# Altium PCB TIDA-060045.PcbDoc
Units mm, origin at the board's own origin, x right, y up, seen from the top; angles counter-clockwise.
Board outline 105 x 122.75 mm, 4 copper layers (Top Layer, Int1 (GND), Int2 (PWR), Bottom Layer), stack 1.547 mm thick; 49 components, 26 nets, 141 pads, 38 vias.
Unrouted connection lines stored in the file: 12.
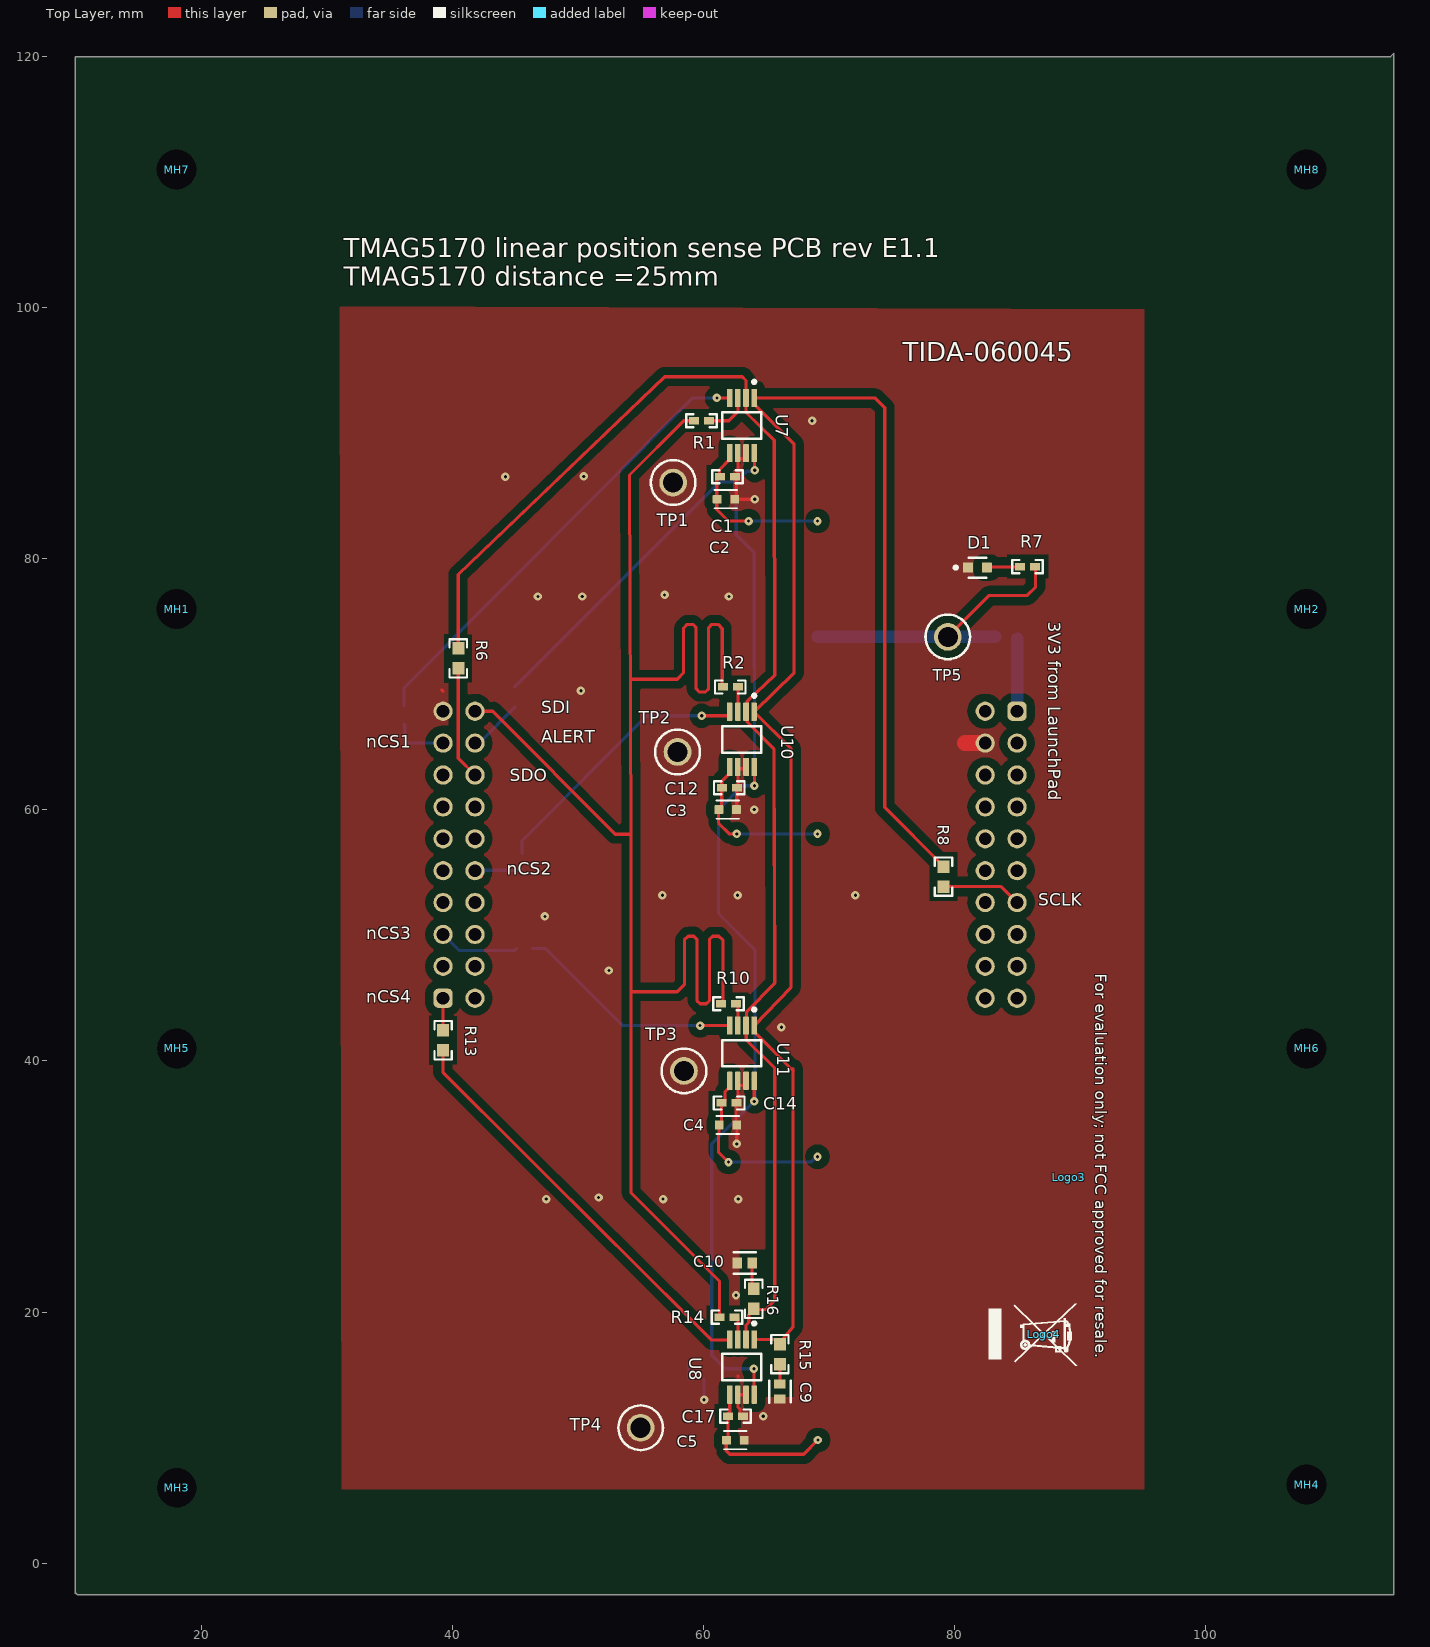
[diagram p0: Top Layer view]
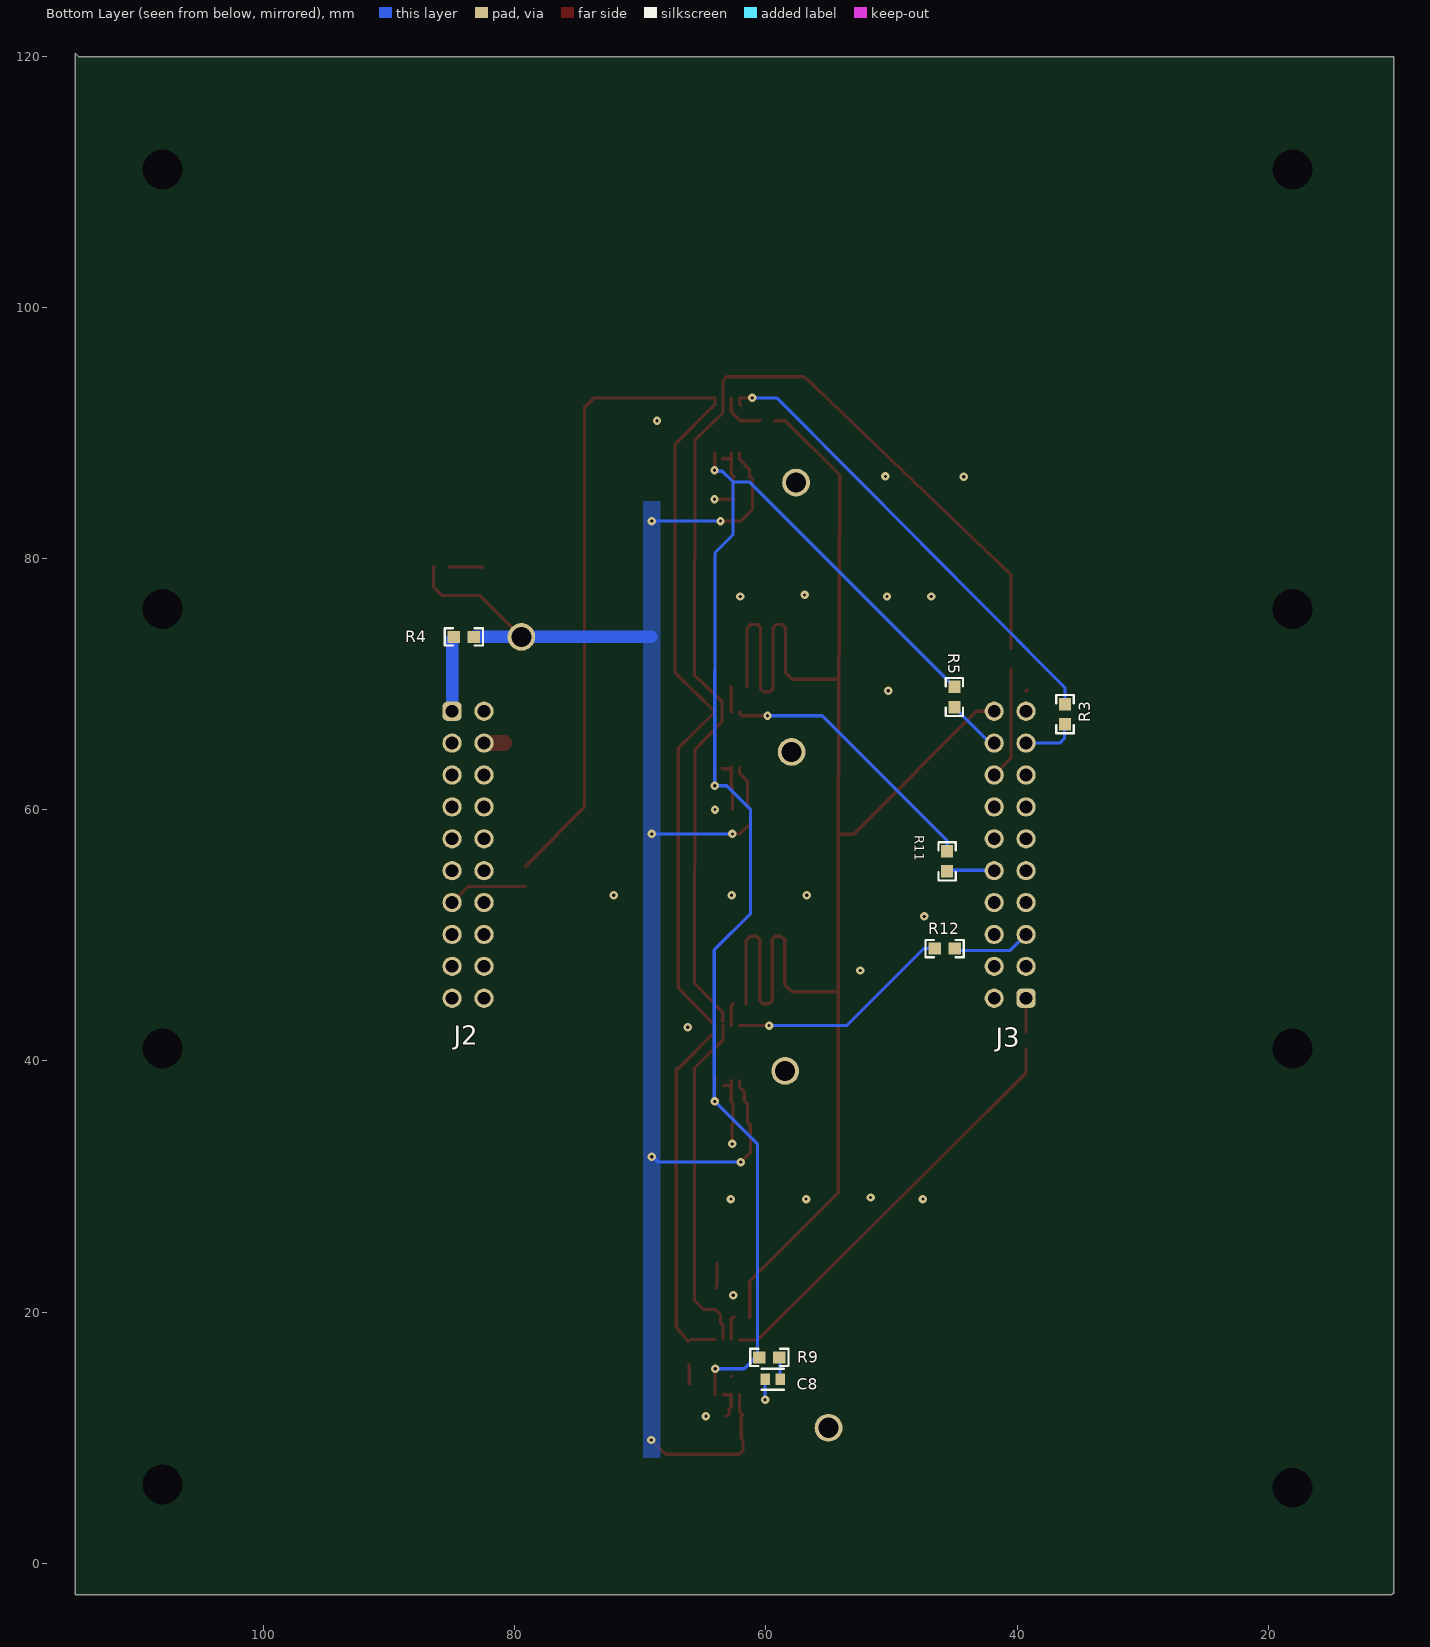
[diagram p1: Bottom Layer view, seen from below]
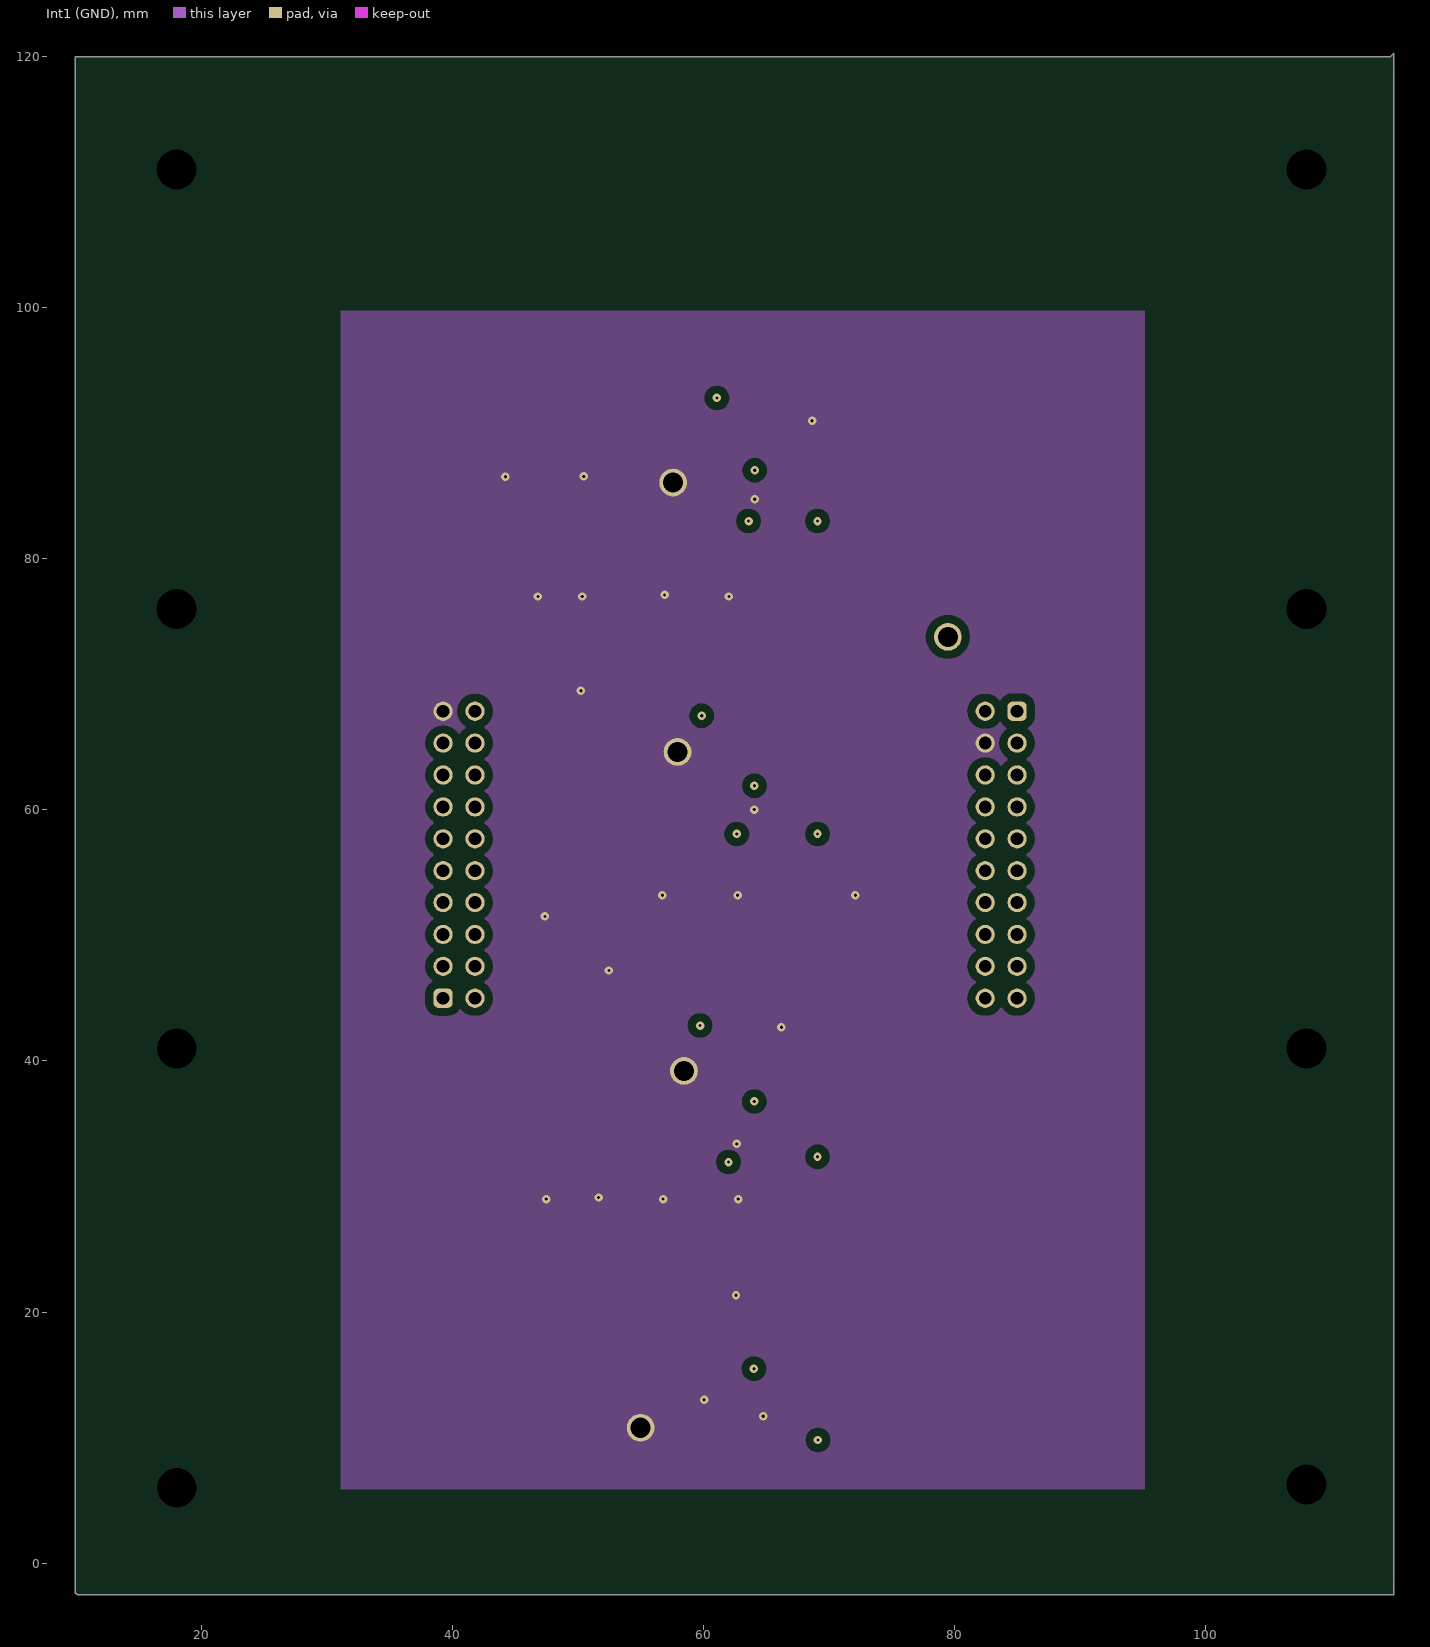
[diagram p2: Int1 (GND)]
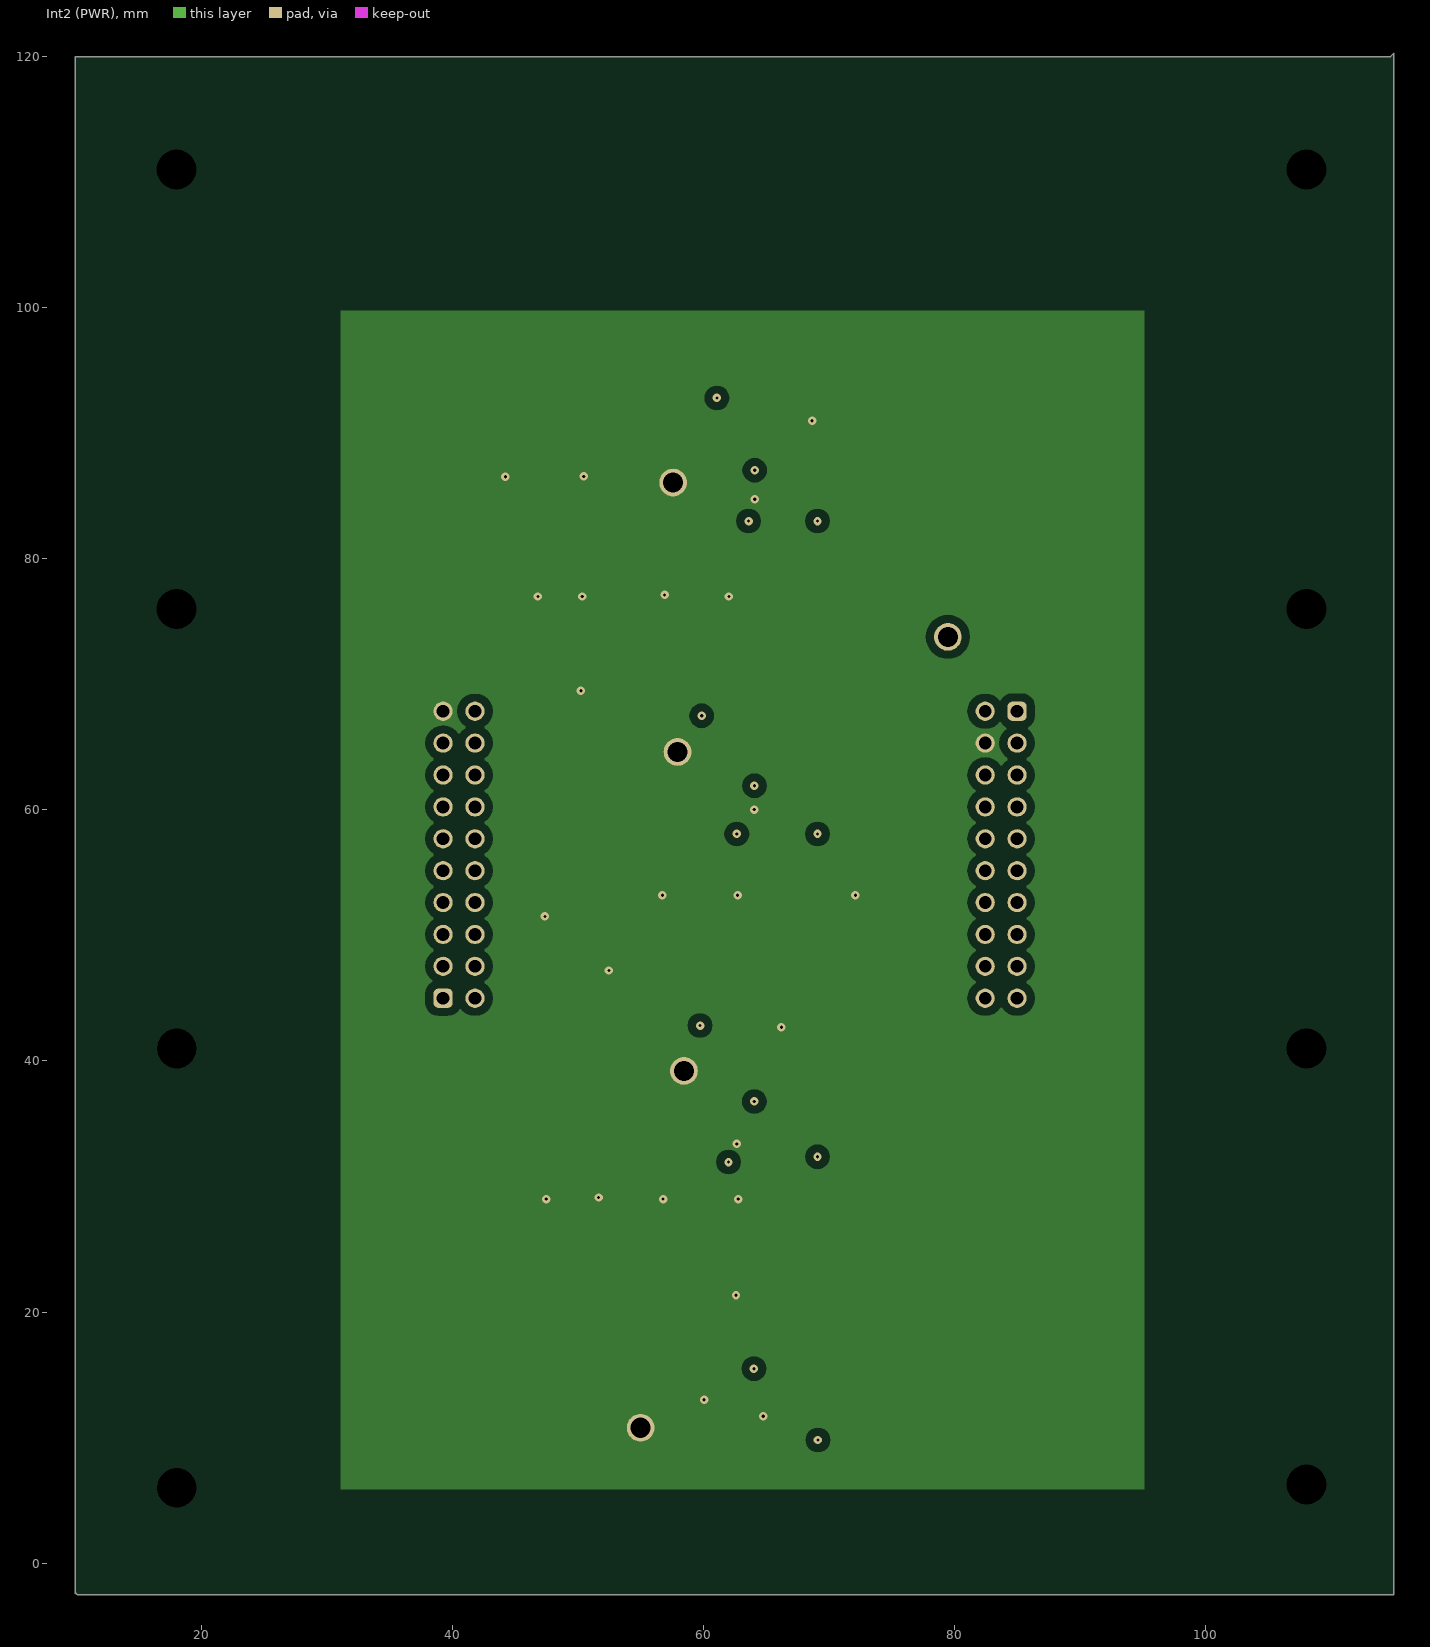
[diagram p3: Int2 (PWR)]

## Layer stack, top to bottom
Top Solder: solder mask 0.0254, SM-001, Dk 4
Top Layer: signal copper 0.035
Dielectric 1: prepreg 0.2083, PP-022, Dk 4.5
Int1 (GND): signal copper 0.035
Dielectric 3: core 0.9906, Core-042, Dk 4.6
Int2 (PWR): signal copper 0.035
Dielectric 5: prepreg 0.2083, PP-022, Dk 4.5
Bottom Layer: signal copper 0.035
Bottom Solder: solder mask 0.0254, SM-001, Dk 4

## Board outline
10,-2.353 10.147,-2.5 115,-2.5 115,120.25 114.75,120 10,120 10,-2.451

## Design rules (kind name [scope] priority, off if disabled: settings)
AcuteAngle [All] p1: minimum=4.50000000000000E+0001 checktracksonly=FALSE
AssemblyTestPointUsage [All] p1: valid=2
BoardOutlineClearance BoardOutlineClearance_MountingHoles [OnCopper and InComponentClass('Mounting Holes')] p1: gap=1 ignorepadtopadclearanceinfootprint=FALSE
BoardOutlineClearance BoardOutlineClearance_Poly [OnCopper and IsPoly] p2: gap=0.635 ignorepadtopadclearanceinfootprint=FALSE
BoardOutlineClearance [OnCopper and Not InComponentClass('Logo') and not InComponentClass('FiducialMark') and not InRegion(1000,500,4000,800) and not InPoly] p3: gap=1.905 ignorepadtopadclearanceinfootprint=FALSE
Clearance Clearance_Keepouts [((IsTrack Or IsArc) And Not InPoly) And IsFree and IsKeepOut vs ((IsTrack Or IsArc) And Not InPoly) And IsFree and IsKeepOut] p1: gap=0 ignorepadtopadclearanceinfootprint=FALSE
Clearance Clearance_Poly [InPolygon] p2: gap=0.635 ignorepadtopadclearanceinfootprint=TRUE
Clearance Clearance_FiducialMark [IsKeepOut and InComponentClass('FiducialMark') vs IsPad and InComponentClass('FiducialMark')] p3: gap=0 ignorepadtopadclearanceinfootprint=FALSE
Clearance [All] p4: gap=0.1 ignorepadtopadclearanceinfootprint=TRUE
ComponentClearance ComponentClearance_MountingHoles_FiducialMarks [InComponentClass('Mounting Holes') vs InComponentClass('FiducialMark')] p1: gap=1.27 collisioncheckmode=3 verticalgap=0.254 showdistances=FALSE
ComponentClearance ComponentClearance_Shunt [InComponentClass('Header') vs InComponentClass('Shunt')] p2: gap=0 collisioncheckmode=3 verticalgap=0 showdistances=FALSE
ComponentClearance ComponentClearance_Logo [InComponentClass('Logo')] p3: gap=1.27 collisioncheckmode=3 verticalgap=0.254 showdistances=FALSE
ComponentClearance ComponentClearance_ScrewToNut [(HasFootprint('NY PMS 440 0025 PH')) vs (HasFootprint('Keystone_1902C'))] p4: gap=0.127 collisioncheckmode=3 verticalgap=0.254 showdistances=FALSE
ComponentClearance ComponentClearance_MountingHoles [InComponentClass('Mounting Holes')] p5: gap=6.35 collisioncheckmode=3 verticalgap=2540 showdistances=FALSE
ComponentClearance ComponentClearance_SmallPassives [HasFootprint('0201*') or HasFootprint('0402*') or HasFootprint('0508') or HasFootprint('0603*') or HasFootprint('0612') or HasFootprint('0805*') or HasFootprint('0815*') or HasFootprint('0830*') or HasFootprint('1206*') or HasFootprint('1210*') or HasFootprint('1808*') or HasFootprint('1812*') or HasFootprint('1825*') or HasFootprint('2010*') or HasFootprint('2220*') or HasFootprint('2225*') or HasFootprint('2512*') or HasFootprint('2728*') or HasFootprint('3518*') vs HasFootprint('0201*') or HasFootprint('0402*') or HasFootprint('0508') or HasFootprint('0603*') or HasFootprint('0612') or HasFootprint('0805*') or HasFootprint('0815*') or HasFootprint('0830*') or HasFootprint('1206*') or HasFootprint('1210*') or HasFootprint('1808*') or HasFootprint('1812*') or HasFootprint('1825*') or HasFootprint('2010*') or HasFootprint('2220*') or HasFootprint('2225*') or HasFootprint('2512*') or HasFootprint('2728*') or HasFootprint('3518*')] p6: gap=0.38 collisioncheckmode=3 verticalgap=0.254 showdistances=FALSE
ComponentClearance ComponentClearance_THtoSMT [IsThruComponent vs IsSMTComponent] p7: gap=1.016 collisioncheckmode=3 verticalgap=0.762 showdistances=FALSE
ComponentClearance ComponentClearance_THtoTH [IsThruComponent vs IsThruComponent] p8: gap=0.762 collisioncheckmode=3 verticalgap=0.762 showdistances=FALSE
ComponentClearance [All] p9: gap=0.762 collisioncheckmode=3 verticalgap=0.254 showdistances=FALSE
DiffPairsRouting [All] p1: maxlimit=2.54 minlimit=0.254 mostfreqgap=0.254 toplayer_minwidth=0.381 toplayer_maxwidth=0.381 toplayer_prefwidth=0.381 midlayer1_minwidth=0.381 midlayer1_maxwidth=0.381 midlayer1_prefwidth=0.381 midlayer2_minwidth=0.381 midlayer2_maxwidth=0.381 midlayer2_prefwidth=0.381 bottomlayer_minwidth=0.381 bottomlayer_maxwidth=0.381 bottomlayer_prefwidth=0.381 maxuncoupledlength=25.4
FabricationTestPointUsage TestPointUsage [All] p1: valid=2 allowmultiple=FALSE
FabricationTestpoint Testpoint [All] p1: side=3 testpointundercomponent=TRUE minsize=1.016 maxsize=2.54 preferedsize=1.524 minholesize=0 maxholesize=1.016 preferedholesize=0.813 testpointgrid=0.025 allowsidetop=TRUE allowsidebottom=TRUE usegrid=TRUE gridtolerance=0
FanoutControl Fanout_LCC [IsLCC] p1: bgadir=Out bgaviamode=Centered fanoutstyle=Auto fanoutdirection=Alternating viagrid=0.025 // Fanout_LCC (Default Rule)
FanoutControl Fanout_BGA [IsBGA] p2: bgadir=Out bgaviamode=Centered fanoutstyle=Auto fanoutdirection=Alternating viagrid=0.025 // Fanout_BGA (Default Rule)
FanoutControl Fanout_Default [All] p4: bgadir=Out bgaviamode=Centered fanoutstyle=Auto fanoutdirection=Alternating viagrid=0.025 // Fanout_Default (Default Rule)
FanoutControl Fanout_Small [(CompPinCount < 5)] p5: bgadir=Out bgaviamode=Centered fanoutstyle=Auto fanoutdirection=OutThenIn viagrid=0.025 // Fanout_Small (Default Rule)
HoleSize [All] p1: absolutevalues=TRUE maxlimit=6.375 minlimit=0.2 maxpercent=80.000 minpercent=20.000
MinimumAnnularRing MinimumAnnularRing_ThermalPadVias [IsVia and InAnyComponent] p1: minimumring=0.15
MinimumAnnularRing [All] p2: minimumring=0.2
MinimumSolderMaskSliver MinimumSolderMaskSliver_Logo [InComponentClass('Logo') vs InComponentClass('Logo')] p1: minsoldermaskwidth=0.018
MinimumSolderMaskSliver [All] p2: minsoldermaskwidth=0.1
PlaneConnect [All] p1: planeconnectstyle=Direct reliefexpansion=0.254 reliefentries=4 reliefconductorwidth=0.254 reliefairgap=0.254
PolygonConnect [All] p1: connectstyle=Direct reliefconductorwidth=0.254 reliefentries=4 polygonreliefangle="90 Angle" airgapwidth=0.254
RoutingLayers [All] p1: top layer_v5=TRUE mid layer 1_v5=FALSE mid layer 2_v5=FALSE bottom layer_v5=TRUE
RoutingVias ThermalPadVias [IsVia and InAnyComponent] p1: holewidth=0.2 width=0.5 viastyle="Through Hole" minholewidth=0.2 minwidth=0.5 maxholewidth=0.33 maxwidth=0.6
RoutingVias [All] p2: holewidth=0.406 width=0.864 viastyle="Through Hole" minholewidth=0.2 minwidth=0.66 maxholewidth=1.016 maxwidth=1.651
SilkToBoardRegionClearance [Not ((IsComment or IsDesignator) And (Hide <> 'False')) and not InRegion(1000,500,4000,800)] p1:
SilkToSilkClearance SilkToSilkClearance_Pb-FreeLogo [(HasFootprint('Pb-Free_Overlay_Medium') OR HasFootprint('Pb-Free_Overlay_Small')) vs (HasFootprint('Pb-Free_Overlay_Medium') OR HasFootprint('Pb-Free_Overlay_Small'))] p1: silktosilkclearance=0
SilkToSilkClearance [All] p2: silktosilkclearance=0.1
SilkToSolderMaskClearance SilkToComponentPadClearance [(IsPad or IsFill or IsRegion) and InAnycomponent] p1: minsilkscreentomaskgap=0.127 clearancetoexposedcopper=TRUE
SilkToSolderMaskClearance "Silk to Solder Mask Opening" [All] p2: minsilkscreentomaskgap=0.1 clearancetoexposedcopper=FALSE
SolderMaskExpansion [All] p1: expansion=0.05 istentingtop=FALSE
UnRoutedNet [All] p1: checkbadconnections=TRUE
Width [All] p1: maxlimit=2.54 minlimit=0.152 preferedwidth=0.254 checkconnectedcopper=TRUE
13 further rules are at their usual default settings.

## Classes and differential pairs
component class Header: J2 J3
component class TIDA-060045: C1 C2 C3 C4 C5 C8 C9 C10 C12 C14 C17 D1 J2 J3 R1 R2 R3 R4 R5 R6 R7 R8 R9 R10 R11 R12 R13 R14 R15 R16 TP1 TP2 TP3 TP4 TP5 U7 U8 U10 U11
component class TIDA-060045_Hardware: Logo3 Logo4 MH1 MH2 MH3 MH4 MH5 MH6 MH7 MH8

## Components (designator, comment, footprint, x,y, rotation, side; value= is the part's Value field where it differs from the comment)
C1 "C0402C104K4RACAUTO" 0402 61.936,86.532 r0 top value=0.1uF
C2 "C1608X7R1E105K080AE" FP-C1608X7R1E105K080AE_0603-MFG 61.81,84.75 r0 top value=1µF
C3 "C1608X7R1E105K080AE" FP-C1608X7R1E105K080AE_0603-MFG 61.947,60.022 r0 top value=1µF
C4 "C1608X7R1E105K080AE" FP-C1608X7R1E105K080AE_0603-MFG 61.973,34.905 r0 top value=1µF
C5 "C1608X7R1E105K080AE" FP-C1608X7R1E105K080AE_0603-MFG 62.566,9.793 r0 top value=1µF
C8 "C0603C330J5GACTU" FP-C0603C-CF-MFG 59.472,14.642 r0 bottom value="33 pF"
C9 "C0603C330J5GACTU" FP-C0603C-CF-MFG 66.106,13.671 r270 top value="33 pF"
C10 "C0603C330J5GACTU" FP-C0603C-CF-MFG 63.298,23.906 r180 top value="33 pF"
C12 "C0402C104K4RACAUTO" 0402 62.081,61.761 r0 top value=0.1uF
C14 "C0402C104K4RACAUTO" 0402 62.064,36.653 r0 top value=0.1uF
C17 "C0402C104K4RACAUTO" 0402 62.571,11.708 r0 top value=0.1uF
D1 "LG L29K-F2J1-24-Z" "FP-LG L29K-F2J1-24-Z_0603-MFG" 81.84,79.3 r0 top
J2 "HTSW-110-14-G-D" Samtec_HTSW-110-14-x-D 83.733,56.427 r180 bottom
J3 "HTSW-110-14-G-D" Samtec_HTSW-110-14-x-D 40.552,56.427 r0 bottom
Logo3 "FCC disclaimer" FCC_disclaimer 89.128,30.75 r270 top
Logo4 "WEEE logo" WEEE_Minimum 87.128,18.25 r270 top
MH1 "MTG_NoPads" NPTH125mil#1 16.31,76 r0 top
MH2 "MTG_NoPads" NPTH125mil#2 96.31,76 r0 top
MH3 "MTG_NoPads" NPTH125mil#1 16.311,6 r0 top
MH4 "MTG_NoPads" NPTH125mil#3 96.311,6 r0 top
MH5 "MTG_NoPads" NPTH125mil#4 18.061,41 r0 top
MH6 "MTG_NoPads" NPTH125mil#4 108.061,41 r0 top
MH7 "MTG_NoPads" NPTH125mil#4 18.06,111 r0 top
MH8 "MTG_NoPads" NPTH125mil#4 108.06,111 r0 top
R1 "RMCF0402FT33R0" 0402 59.869,91 r180 top value=33.0
R2 "RMCF0402FT33R0" 0402 62.161,69.792 r180 top value=33.0
R3 "RMCF0603ZT0R00" 0603 36.178,67.618 r90 bottom value=0
R4 "RMCF0603ZT0R00" 0603 84.061,73.782 r0 bottom value=0
R5 "RMCF0603ZT0R00" 0603 44.991,68.992 r270 bottom value=0
R6 "RMCF0603ZT0R00" 0603 40.493,72.07 r270 top value=0
R7 "ERA2AEB222X" 0402 85.837,79.373 r0 top value=2.20k
R8 "RMCF0603ZT0R00" 0603 79.144,54.687 r270 top value=0
R9 "M55342K12B49D9T" 0603 59.728,16.387 r180 bottom value=49.9
R10 "RMCF0402FT33R0" 0402 62.013,44.552 r180 top value=33.0
R11 "RMCF0603ZT0R00" 0603 45.568,55.898 r270 bottom value=0
R12 "RMCF0603ZT0R00" 0603 45.765,48.948 r0 bottom value=0
R13 "RMCF0603ZT0R00" 0603 39.282,41.65 r270 top value=0
R14 "RMCF0402FT33R0" 0402 61.896,19.592 r180 top value=33.0
R15 "M55342K12B49D9T" 0603 66.106,16.65 r270 top value=49.9
R16 "M55342K12B49D9T" 0603 64.025,21.056 r90 top value=49.9
TP1 "5013" Keystone5013 57.606,86.075 r270 top
TP2 "5013" Keystone5013 57.956,64.611 r270 top
TP3 "5013" Keystone5013 58.468,39.209 r270 top
TP4 "5013" Keystone5013 55.018,10.782 r270 top
TP5 "5013" Keystone5013 79.485,73.782 r0 top
U7 "TMAG5170A1QDGKR" DGK0008A-MFG 63.086,90.617 r270 top
U8 "TMAG5170A1QDGKR" DGK0008A-MFG 63.086,15.617 r270 top
U10 "TMAG5170A1QDGKR" DGK0008A-MFG 63.086,65.617 r270 top
U11 "TMAG5170A1QDGKR" DGK0008A-MFG 63.086,40.617 r270 top

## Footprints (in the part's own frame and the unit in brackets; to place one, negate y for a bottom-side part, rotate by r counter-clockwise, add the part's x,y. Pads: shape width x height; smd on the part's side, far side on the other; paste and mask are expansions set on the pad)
0402 [mm] "0402 from SM-752 data"
  rect 0.8x0.6 smd: 1(-0.6,0) 2(0.6,0)
  silkscreen extent -1.22,-0.52 1.22,0.52, body extent -0.55,-0.3 0.55,0.3, height 0.6
0603 [mm] "0603 from SM-752 data"
  rect 1x0.95 smd: 1(-0.8,0) 2(0.8,0)
  silkscreen extent -1.52,-0.69 1.52,0.69, body extent -0.87,-0.47 0.87,0.47, height 1
DGK0008A-MFG [mm]
  rrect22% 1.45x0.45 smd paste+0 mask+0: 1(-2.2,0.975) 2(-2.2,0.325) 3(-2.2,-0.325) 4(-2.2,-0.975) 5(2.2,-0.975) 6(2.2,-0.325) 7(2.2,0.325) 8(2.2,0.975)
  silkscreen extent -3.6,-1.55 1.05,1.55, body extent -3.03,-1.8 3.03,1.8, height 0.25
FCC_disclaimer [mm]
FP-C0603C-CF-MFG [mm]
  rect 0.75x0.9 smd paste+0 mask+0: 1(-0.6,0) 2(0.6,0)
  silkscreen extent -0.87,-0.85 0.88,0.85, body extent -0.8,-0.4 0.8,0.4, height 0.87
FP-C1608X7R1E105K080AE_0603-MFG [mm]
  rrect14% 0.7x0.7 smd paste+0 mask+0: 1(-0.7,0) 2(0.7,0)
  silkscreen extent -0.9,-0.72 0.9,0.72, body extent -1.15,-0.58 1.15,0.58, height 0.25
"FP-LG L29K-F2J1-24-Z_0603-MFG" [mm]
  rrect13% 0.8x0.8 smd paste-1000 mask+0: 1(-0.75,0) 2(0.75,0)
  silkscreen extent -1.85,-0.8 0.7,0.8, body extent -1.25,-0.55 1.25,0.55, height 0.25
Keystone5013 [mil] "Keystone Multipurpose loops"
  round 87 hole 63: 1(0,0)
  silkscreen extent -70,-70 70,70, body extent -63,-63 63,62, height 319
NPTH125mil#1 [mil]
  round 120 hole 125 unplated mask+15: 1(68.9,0)
NPTH125mil#2 [mil]
  round 120 hole 125 unplated mask+15: 1(462.6,0)
NPTH125mil#3 [mil]
  round 120 hole 125 unplated mask+15: 1(462.6,9.84)
NPTH125mil#4 [mil]
  round 120 hole 125 unplated mask+15: 1(0,0)
Samtec_HTSW-110-14-x-D [mm] "Header, 2.54mm, 10x2, TH"
  rrect50% 1.53x1.53 hole 1.02: 1(-1.27,11.43)
  round 1.53 hole 1.02: 2(1.27,11.43) 3(-1.27,8.89) 4(1.27,8.89) 5(-1.27,6.35) 6(1.27,6.35) 7(-1.27,3.81) 8(1.27,3.81) 9(-1.27,1.27) 10(1.27,1.27) 11(-1.27,-1.27) 12(1.27,-1.27) 13(-1.27,-3.81) 14(1.27,-3.81) 15(-1.27,-6.35) 16(1.27,-6.35) 17(-1.27,-8.89) 18(1.27,-8.89) 19(-1.27,-11.43) 20(1.27,-11.43)
  body extent -2.51,-12.7 2.51,12.7, height 10.67
WEEE_Minimum [mm] "WEEElie bin"
  silkscreen extent -2.42,-4.38 2.52,2.65

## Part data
C1 C12 C14 C17: library part CMP-0006237-2, "CAP, CERM, 0.1 uF, 16 V, +/- 10%, X7R, AEC-Q200 Grade 1, 0402", Cap_Case=0402, Manufacturer=Kemet, Supplier Part Number 1=399-6828-1-ND, TempCo=X7R, Tolerance_%=10%, Value1=Unknown, Value2=16V, ValueDisplayed=0.1uF
C2 C3 C4 C5: library part CMP-0116394-1, "C Series 0603 1 uF 25 V ±10 %Tolerance X7R SMT Multilayer Ceramic Capacitor", Digikey Part Number=445-173615-1-ND, Manufacturer=TDK, Mouser Part Number=810-C1608X7R1E105KAE, Operating Temperature Range="-55°C to +125°C", TempCo=15%, Temperature Characteristic=X7R, Tolerance_%=10%, ValueDisplayed=1uF
C8 C9 C10: library part CMP-2006-03168-3, "Capacitor; Ceramic; Cap; 33.0pF; Tol 5%; SMT; Vol-Rtg 50V; C0G; Tape and Reel", Capacitance="33 pF", Manufacturer=KEMET, Package=C0603C-CF, Temperature="-55°C to +125°C", Temperature Characteristic=C0G, Temperature Coefficient=30ppm/°C, Temperature Range High=+125°C, Temperature Range Low=-55°C, Tolerance=0.05, Voltage Rating="50 V"
D1: library part CMP-0088492-1, "Green 570nm LED Indication - Discrete 1.7V 0603 (1608 Metric)", Color=Green, Digikey Part Number=475-3118-1-ND, Forward Current=2mA, Manufacturer=Osram, Mouser Part Number=720-LGL29KF2J124Z, Operating Temperature Range="-40°C to +100°C"
J2 J3: library part CMP-0082589-1, "Header, 2.54mm, 10x2, Gold, TH", Color=Natural, Manufacturer=Samtec, Supplier Part Number 1=SAM12662-ND
Logo3: library part CMP-0074847-1, "FCC_disclaimer"
Logo4: library part CMP-0074769-1
MH1 MH2 MH3 MH4 MH5 MH6 MH7 MH8: library part CMP-0078424-2, "PCB Mounting Hole, No Pad", Manufacturer=Any, PartNumber=N/A
R1 R2 R10 R14: library part CMP-0026759-1, "RES, 33.0, 1%, 0.063 W, AEC-Q200 Grade 0, 0402", Manufacturer="Stackpole Electronics Inc", Power_W=63mW, Supplier Part Number 1=RMCF0402FT33R0CT-ND, TempCo="100 ppm/C", Tolerance_%=1%, Value2=0.063W, Value_Code=33R0, ValueDisplayed=33.0
R3 R4 R5 R6 R8 R11 R12 R13: library part CMP-0023343-3, "RES, 0, 1%, 0.1 W, AEC-Q200 Grade 0, 0603", Manufacturer="Stackpole Electronics Inc", Power_W=100mW, Supplier Part Number 1=RMCF0603ZT0R00CT-ND, TempCo=ppm/C, Tolerance_%=1%, Value2=0.1W, Value_Code=0
R7: library part CMP-0074667-1, "RES, 2.20 k, 0.1%, 0.0625 W, AEC-Q200 Grade 0, 0402", Manufacturer=Panasonic, Power_W=62.5mW, Supplier Part Number 1=P2.2KDCCT-ND, TempCo="25 ppm/C", Tolerance_%=0.1%, Value2=0.0625W, Value_Code=2k20, ValueDisplayed=2.20k
R9 R15 R16: library part CMP-0080492-1, "RES, 49.9, 1%, 0.1 W, 0603", Manufacturer="TT Electronics/IRC", Power_W=100mW, TempCo="100 ppm/C", Tolerance_%=1%, Value2=0.1W, Value_Code=49R9, ValueDisplayed=49.9
TP1 TP2 TP3 TP4 TP5: library part CMP-0055150-1, "Test Point, Multipurpose, Orange, TH", Color=Orange, Manufacturer=Keystone, Supplier Part Number 1=36-5013-ND
U7 U8 U10 U11: library part CMP-0088287-1, "3-Axis Linear Hall Effect Sensor With SPI Interface", Manufacturer="Texas Instruments", Max Supply Voltage=5.5V, Min Supply Voltage=1.65V, Operating Supply Current=0.000005-4mA, Operating Temperature Range="-40°C to +150°C"

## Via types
v1: diameter 0.67, hole 0.254, Top Layer to Bottom Layer, 38 vias

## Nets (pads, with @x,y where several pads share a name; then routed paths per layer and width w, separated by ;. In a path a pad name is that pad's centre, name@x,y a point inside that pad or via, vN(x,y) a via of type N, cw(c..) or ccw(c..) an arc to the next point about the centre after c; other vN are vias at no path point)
3V3: C1.1 C2.1 C3.1 C4.1 C5.1 C12.1 C14.1 C17.1 R4.1 R7.2 TP5.1 U7.5 U8.5 U10.5 U11.5 | length 77.9
  Top Layer w0.254: C17.1@61.861,11.817 62.111,12.067 U8.5 ; C17.1 61.971,9.924 61.84,9.793 61.84,8.946 62.111,8.674 68.004,8.674 v1(69.134,9.804) ; v1(62.013,31.941) 61.221,32.733 61.221,33.266 61.248,34.905 61.464,35.121 C14.1 61.564,36.653 61.737,36.826 61.737,37.45 61.739,37.451 61.739,37.545 62.111,37.917 U11.5 ; U10.5 62.111,62.917 61.476,62.282 61.476,61.766 C12.1 61.481,60.281 61.221,60.022 61.221,58.948 62.081,58.089 v1(62.673,58.089) ; U7.5 62.111,87.917 61.301,87.106 61.301,86.567 C1.1 61.236,86.532 61.084,86.381 61.084,84.75 61.084,83.929 62.013,83 v1(63.618,83) ; TP5.1 82.788,77.084 85.811,77.084 86.477,77.75 86.477,79.333 R7.2
  Bottom Layer w0.254: v1(62.013,31.941) 68.565,31.941 68.99,32.366 v1(69.103,32.366) v1@69.066,32.329 ; v1(62.673,58.089) v1(69.103,58.089) ; v1(63.618,83) v1(69.103,83) ; 69.103,73.75 69.134,73.782
  Bottom Layer w1: 69.134,73.782 TP5.1 R4.1
GND: C1.2 C2.2 C3.2 C4.2 C5.2 C8.2 C9.2 C10.2 C12.2 C14.2 C17.2 D1.1 J2.4 J3.19 TP1.1 TP2.1 TP3.1 TP4.1 U7.6 U7.7 U8.6 U8.7 U10.6 U10.7 U11.6 U11.7 | length 22.5
  Top Layer w0.254: 39.176,69.549 39.282,69.442 ; C2.2@62.536,84.75 C2.2@62.628,84.842 ; C3.2@62.673,60.022 62.673,61.753 C12.2 62.761,61.841 U10.6 62.859,63.319 U10.6@62.859,63.275 ; v1(62.68,33.393) 62.698,34.776 62.699,34.778 62.699,34.905 62.614,34.99 62.614,36.603 C14.2 62.761,36.749 U11.6@62.761,38.05 ; U11.6@62.739,38.05 U11.6@62.761,38.05 ; 62.761,14.871 62.773,14.883 ; U11.6 U11.6@62.761,38.05 ; U7.6 U7.6@62.761,87.996 ; U10.6@62.829,63.275 U10.6@62.859,63.275 ; C17.2 63.11,11.708 62.937,11.881 62.937,12.258 62.761,12.433 U8.6 U8.7 ; U11.7@63.389,38.05 U11.6@62.761,38.05 ; U7.7@63.44,87.967 62.79,87.967 U7.6@62.761,87.996 ; U10.7@63.479,63.275 U10.6@62.859,63.275 ; v1@64.314,84.75 62.72,84.75 C2.2@62.628,84.842 ; 80.837,65.295 80.86,65.317 ; C2.2@62.628,84.842 C1.2@62.628,86.572 ; C1.2@62.628,86.572 62.588,86.532 C1.2 62.628,86.625 C1.2@62.628,86.572 ; C1.2@62.628,86.572 62.761,86.705 U7.6@62.761,87.996
  Top Layer w1.27: 80.86,65.317 J2.4
  Bottom Layer w0.254: v1(60.072,13.01) C8.2
  other v1: 64.783,11.701 62.613,21.33 47.501,28.996 56.802,28.996 62.791,28.996 51.667,29.123 66.233,42.69 52.49,47.204 47.386,51.515 56.751,53.196 62.74,53.196 72.128,53.196 64.061,60.022 50.256,69.492 46.832,76.996 50.359,76.996 62.044,76.996 56.925,77.123 64.103,84.75 44.243,86.532 50.486,86.567 68.678,91
MISO: J3.20 R1.2 R2.2 R10.2 R14.2 | length 146.2
  Top Layer w0.254: J3.20 43.234,67.857 52.992,58.062 54.25,58.062 ; 54.197,70.407 57.927,70.407 58.435,70.914 58.435,74.471 58.735,74.771 59.185,74.771 59.435,74.521 59.435,69.641 59.685,69.391 60.184,69.391 60.435,69.642 60.435,74.521 60.685,74.771 61.185,74.771 61.52,74.435 R2.2@61.52,69.792 ; R1.2 58.454,91 54.128,86.674 54.25,58.062 ; R14.2 61.296,22.451 54.25,29.498 54.25,45.509 ; R10.2@61.585,44.552 61.585,49.605 61.25,49.941 60.75,49.941 60.5,49.691 60.5,44.811 60.249,44.561 59.75,44.561 59.5,44.811 59.5,49.691 59.25,49.941 58.8,49.941 58.5,49.641 58.5,46.084 57.925,45.509 54.25,45.509 ; 54.25,45.509 54.25,58.062
MOSI: R6.1 R16.1 U7.2 U8.2 U10.2 U11.2 | length 117.4
  Top Layer w0.254: R6.1 40.493,78.75 56.925,94.5 63.114,94.5 63.411,94.203 U7.2 63.411,91.656 65.664,89.438 65.694,70.727 63.509,68.662 63.509,66.999 65.644,64.82 65.694,46.204 63.44,43.87 U11.2@63.44,43.163 ; U8.2 63.411,18.953 63.627,19.169 63.627,19.808 64.025,20.206 64.974,20.206 65.694,20.925 65.694,39.438 63.411,41.679 ; U11.2 63.423,41.667
nALERT: R5.1 R9.1 U7.8 U8.8 U10.8 U11.8 | length 111.3
  Top Layer w0.254: U11.8@63.993,38.523 64.061,38.455 U11.8 64.067,38.411 64.067,36.785 v1(64.073,36.78) ; v1(64.039,15.49) 64.05,15.479 64.05,13.428 U8.8 ; U10.8 v1(64.082,61.919) ; U7.8 64.082,88.396 64.082,87.074 v1(64.103,87.053)
  Bottom Layer w0.254: R5.1 44.991,69.817 45.339,70.165 45.364,70.165 61.321,86.122 62.628,86.122 ; v1(64.039,15.49) 61.739,15.49 60.686,16.543 60.686,33.393 v1(64.073,36.78) 64.116,36.823 64.116,48.848 61.221,51.742 61.221,60.022 63.119,61.919 v1(64.082,61.919) 64.061,80.47 62.628,81.903 62.628,86.122 ; v1(64.103,87.053) 64.023,86.974 63.479,86.974 62.628,86.122
nCS1: R3.2 U7.4 | length 37.6
  Top Layer w0.254: v1(61.089,92.817) U7.4 62.111,92.358 U7.4@62.013,92.26
  Bottom Layer w0.254: R3.2@36.178,68.268 36.178,69.742 59.153,92.817 v1(61.089,92.817)
nCS2: R11.1 U10.4 | length 22
  Top Layer w0.254: v1(59.878,67.5) 61.922,67.5 62.111,67.689 U10.4
  Bottom Layer w0.254: R11.1@45.606,56.513 45.566,56.553 45.566,57.545 55.513,67.491 v1(59.878,67.5) v1@59.787,67.591
nCS3: R12.2 U11.4 | length 18.2
  Top Layer w0.254: v1(59.75,42.817) U11.4
  Bottom Layer w0.254: R12.2@46.415,48.948 47.453,48.948 53.584,42.817 v1(59.75,42.817)
nCS4: R13.2 U8.4 | length 33.6
  Top Layer w0.254: R13.2@39.282,41 39.282,39.076 45.612,32.746 60.686,17.768 62.062,17.768 U8.4
NetC8_1: C8.1 R9.2 | length 1.4
  Bottom Layer w0.254: C8.1 58.872,15.939 R9.2@58.912,15.979
NetC9_1: C9.1 R15.2 | length 1.5
  Top Layer w0.254: C9.1 R15.2@66.106,15.8
NetC10_1: C10.1 R16.2 | length 2.1
  Top Layer w0.254: C10.1 63.898,22.033 R16.2@64.025,21.906
NetD1_2: D1.2 R7.1 | length 2.7
  Top Layer w0.254: D1.2 82.626,79.336 85.2,79.336 R7.1
NetJ2_1: J2.1 R4.2 | length 6
  Bottom Layer w0.254: R4.2 R4.2@85.003,73.64
  Bottom Layer w1: J2.1 R4.2@85.003,73.64
NetJ2_13: J2.13 R8.2 | length 6.4
  Top Layer w0.254: R8.2 83.733,53.887 J2.13
NetJ3_1: J3.1 R13.1 | length 2.7
  Top Layer w0.254: R13.1@39.282,42.3 J3.1
NetJ3_5: J3.5 R12.1 | length 6.4
  Bottom Layer w0.254: J3.5 40.552,48.807 44.974,48.807 R12.1@45.115,48.948
NetJ3_10: J3.10 R11.2 | length 4.3
  Top Layer w0.254: J3.10 J3.10@41.85,55.185 ; J3.10@42.33,54.675 J3.10@42.33,55.157
  Bottom Layer w0.254: J3.10 41.85,55.185 45.578,55.185 R11.2@45.606,55.213
NetJ3_16: J3.16 R6.2 | length 9
  Top Layer w0.254: R6.2 40.493,64.107 J3.16
NetJ3_17: J3.17 R3.1 | length 4.5
  Bottom Layer w0.254: R3.1 36.228,66.768 36.228,65.682 36.593,65.317 J3.17 ; J3.17@39.534,65.251 J3.17@39.6,65.317
NetJ3_18: J3.18 R5.2 | length 4.4
  Bottom Layer w0.254: J3.18 42.141,65.317 44.991,68.167 R5.2
NetR1_1: R1.1 U7.3 | length 3.7
  Top Layer w0.254: R1.1 62.044,91 62.761,91.717 U7.3
NetR2_1: R2.1 U10.3 | length 2
  Top Layer w0.254: U10.3 R2.1
NetR10_1: R10.1 U11.3 | length 1.8
  Top Layer w0.254: R10.1 62.761,44.404 U11.3
NetR14_1: R14.1 U8.3 | length 2.1
  Top Layer w0.254: R14.1 62.588,19.592 62.761,19.419 U8.3 ; R14.1@62.635,19.592 R14.1@62.761,19.466
SCLK: R8.1 R15.1 U7.1 U8.1 U10.1 U11.1 | length 133.1
  Top Layer w0.254: U8.1 R15.1@66.003,17.817 ; U10.1 67.24,70.914 67.24,89.138 64.061,92.317 U7.1 73.67,92.817 74.463,92.025 74.463,60.193 79.144,55.512 R8.1 ; U10.1@64.103,67.757 66.984,64.91 66.984,45.841 U11.1 64.061,42.317 67.15,39.228 ; R15.1@66.19,17.654 67.15,18.791 67.15,39.228 ; 67.15,39.384 67.15,39.228 ; 67.169,39.209 67.15,39.228
pads on no net: J2.2 J2.3 J2.5 J2.6 J2.7 J2.8 J2.9 J2.10 J2.11 J2.12 J2.14 J2.15 J2.16 J2.17 J2.18 J2.19 J2.20 J3.2 J3.3 J3.4 J3.6 J3.7 J3.8 J3.9 J3.11 J3.12 J3.13 J3.14 J3.15 MH1.1 MH2.1 MH3.1 MH4.1 MH5.1 MH6.1 MH7.1 MH8.1

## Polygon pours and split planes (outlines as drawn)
GND on Top Layer "GND_TOP_LAYER" (solid, remove dead copper, pour order 49): 31.211,5.884 95.128,5.884 95.128,99.875 31.064,100.118
GND on Int2 (PWR) "GND_mid2" (solid, pour order 34): 31.128,5.884 95.128,5.884 95.128,99.75 31.128,99.75
GND on Int1 (GND) "GND_mid1" (solid, pour order 32): 31.128,5.884 95.172,5.884 95.172,99.75 31.128,99.75
3V3 on Bottom Layer "3v3_TMAGS" (solid, remove dead copper, pour order 31): 69.794,84.588 69.794,8.402 68.411,8.402 68.411,84.588

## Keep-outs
Keep-Out Layer:
  text ".Layer_Name" at 14.656,-21.806 h1.52

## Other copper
Top Layer:
  text ".Layer_Name" at 14.656,-21.806 h1.52
Bottom Layer:
  text ".Layer_Name" at 14.656,-21.806 h1.52

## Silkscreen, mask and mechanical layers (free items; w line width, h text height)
Top Overlay:
  text "TMAG5170 linear position sense PCB rev E1.1 / TMAG5170 distance =25mm" at 31.378,101.75 h1.52
  text "TIDA-060045" at 75.878,95.75 h1.52
  text "3V3 from LaunchPad" at 87.472,74.979 h1 r270
  text "SDI" at 47.092,67.687 h1
  text "ALERT" at 47.092,65.362 h1
  text "nCS1" at 33.172,64.951 h1
  text "SDO" at 44.601,62.299 h1
  text "nCS2" at 44.37,54.813 h1
  text "SCLK" at 86.681,52.369 h1
  text "nCS3" at 33.172,49.712 h1
  text "nCS4" at 33.172,44.626 h1
  text ".Layer_Name" at 14.656,-21.806 h1.52
Bottom Overlay:
  text ".Layer_Name" at 14.656,-21.806 h1.52
Top Paste:
  text ".Layer_Name" at 14.656,-21.806 h1.52
Bottom Paste:
  text ".Layer_Name" at 14.656,-21.806 h1.52
Top Solder:
  text ".Layer_Name" at 14.656,-21.806 h1.52
  text ".Layer_Name" at 14.656,-21.806 h1.52
Bottom Solder:
  text ".Layer_Name" at 14.656,-21.806 h1.52
Drill Guide:
  text ".Layer_Name" at 14.656,-21.806 h1.52
M1 Board Outline:
  lines w0.254: 10,120 10,120 ; 10,120 10,-2.451 10.049,-2.5 115,-2.5 115,119.999 ; 10,120 114.999,120 ; 114.999,120 115,119.999
  text "TMAG5170_25mm_4u.PcbDoc" at -1,128 h1.52
M2 Board Dimensions:
  rectangle: 0,-6.985 3.175,-3.81
  rectangle: 3.175,-10.16 12.7,-6.985
  lines w0.178: 0,-6.985 25.4,-6.985 ; 3.175,-10.16 3.175,-3.81 ; 6.35,-10.16 6.35,-3.81 ; 12.7,-10.16 12.7,-3.81 ; 19.05,-10.16 19.05,-3.81 ; 0,-10.16 25.4,-10.16 25.4,-3.81 0,-3.81 0,-10.16
  text ".Layer_Name" at 14.656,-21.806 h1.52
M3 3D STEP Top:
  text ".Layer_Name" at 14.656,-21.806 h1.52
M4 3D STEP Bottom:
  text ".Layer_Name" at 14.656,-21.806 h1.52
M5 Assembly Top:
  lines w0.254: -7.417,-23.626 160.223,-23.626 ; -7.417,-18.462 160.274,-18.462 ; -7.417,-13.297 -7.417,-28.791 94.31,-28.791 160.274,-28.791 160.274,-13.297 -7.404,-13.297 -7.404,-28.791 32.614,-28.791 ; 55.194,-28.791 55.194,-13.297 ; 87.376,-18.462 87.376,-13.297 ; 108.712,-18.462 108.712,-13.297 ; 124.511,-28.956 124.511,-23.804
  text "COMPONENTS MARKED 'DNP' SHOULD NOT BE POPULATED." at 29.299,-8.09 h1.52
  text "ASSEMBLY VARIANT:" at 29.286,-11.024 h1.52
  text ".VariantName" at 55.601,-11.024 h1.52
  text "PCB VIEWED FROM TOP SIDE" at -5.804,-16.654 h1.52
  text "BOARD #:" at 57.099,-16.654 h1.52
  text ".PRJ_Number" at 70.955,-16.654 h1.52
  text "REV:" at 92.405,-16.654 h1.52
  text ".PCB_Rev" at 99.809,-16.654 h1.52
  text "SVN REV:" at 113.69,-16.654 h1.52
  text ".VersionControl_RevNumber" at 126.543,-16.654 h1.52
  text "TID #:" at 57.099,-21.819 h1.52
  text ".TID" at 70.955,-21.819 h1.52
  text "PLOT NAME =" at -5.804,-27.034 h1.52
  text ".plot_File_Name" at 14.656,-27.034 h1.52
  text "GENERATED    :" at 57.15,-27.034 h1.52
  text ".Print_Date" at 79.235,-27.034 h1.52
  text ".Print_Time" at 97.752,-27.034 h1.52
  text "TEXAS INSTRUMENTS" at 129.87,-27.034 h1.52
M6 Assembly Bottom:
  lines w0.254: -7.429,-18.474 160.261,-18.474 ; -7.379,-23.639 160.261,-23.639 ; 28.334,-28.969 28.334,-23.817 ; 44.133,-18.474 44.133,-13.31 ; 65.468,-18.474 65.468,-13.31 ; 97.65,-28.804 97.65,-13.31 ; 120.231,-28.804 160.249,-28.804 160.249,-13.31 -7.429,-13.31 -7.429,-28.804 58.534,-28.804 160.261,-28.804 160.261,-13.31
  text "COMPONENTS MARKED 'DNP' SHOULD NOT BE POPULATED." at 154.991,-8.077 h1.52
  text ".VariantName" at 128.473,-11.024 h1.52
  text "ASSEMBLY VARIANT:" at 154.864,-11.024 h1.52
  text ".VersionControl_RevNumber" at 26.302,-16.667 h1.52
  text "SVN REV:" at 39.154,-16.667 h1.52
  text ".PCB_Rev" at 53.035,-16.667 h1.52
  text "REV:" at 60.439,-16.667 h1.52
  text ".PRJ_Number" at 81.89,-16.667 h1.52
  text "BOARD #:" at 95.745,-16.667 h1.52
  text "PCB VIEWED FROM BOTTOM SIDE" at 158.648,-16.667 h1.52
  text ".TID" at 81.89,-21.831 h1.52
  text "TID #:" at 95.745,-21.831 h1.52
  text "TEXAS INSTRUMENTS" at 22.974,-27.047 h1.52
  text ".Print_Time" at 55.093,-27.047 h1.52
  text ".Print_Date" at 73.609,-27.047 h1.52
  text "GENERATED    :" at 95.694,-27.047 h1.52
  text ".plot_File_Name" at 138.189,-27.047 h1.52
  text "PLOT NAME =" at 158.648,-27.047 h1.52
M9 Title Sheet:
  drawing of 57 lines, arcs and shapes, not listed
  text "1" at 18.792,204.127 h1.78
  text "2" at 82.182,204.127 h1.78
  text "3" at 145.411,204.127 h1.78
  text "4" at 209.08,204.127 h1.78
  text "5" at 272.555,204.127 h1.78
  text "6" at 336.182,204.127 h1.78
  text "A" at -10.579,175.095 h1.78
  text "A" at 365.341,175.095 h1.78
  text "B" at -10.579,114.643 h1.78
  text "B" at 365.341,114.643 h1.78
  text "C" at -10.579,54.318 h1.78
  text "C" at 365.341,54.318 h1.78
  text "PROJECT TITLE:" at 288.125,7.048 h1.14
  text ".PRJ_Title" at 289.395,3.662 h1.78
  text "DESIGNED FOR:" at 288.125,-0.597 h1.14
  text ".PRJ_Customer" at 289.395,-4.153 h1.78
  text "D" at -10.579,-5.88 h1.78
  text "D" at 365.341,-5.88 h1.78
  text "FILE NAME:" at 288.125,-8.217 h1.14
  text ".PCB_File_Name_No_Path" at 289.395,-11.265 h1.78
  text "Texas Instruments (TI) and/or its licensors do not warrant the accuracy or completeness of this specification" at 161.9,-15.376 h1.14
  text "ENGINEER:" at 288.125,-15.583 h1.14
  text "LAYOUT BY:" at 326.352,-15.583 h1.14
  text "or any information contained therein. TI and/or its licensors do not warrant that this design will meet" at 160.757,-18.237 h1.14
  text ".PRJ_Engineer" at 289.395,-19.52 h1.78
  text ".PCB_Layout" at 327.635,-19.52 h1.78
  text "the specifications, will be suitable for your application or fit for any particular purpose, or will operate in" at 160.757,-21.099 h1.14
  text ".Layer_Name" at 14.656,-21.806 h1.52
  text "ALTIUM DESIGNER VERSION:" at 326.352,-23.457 h1.14
  text "an implementation. TI and/or its licensors do not warrant that the design is production worthy. You should" at 160.757,-23.961 h1.14
  text "completely validate and test your design implementation to confirm the system functionality for your application." at 161.9,-26.822 h1.14
  text ".print_Scale" at 289.395,-26.843 h1.78
  text ".Application_BuildNumber" at 327.635,-26.843 h1.78
  text "1" at 18.792,-32.093 h1.78
  text "2" at 82.182,-32.093 h1.78
  text "3" at 145.411,-32.093 h1.78
  text "4" at 209.08,-32.093 h1.78
  text "5" at 272.555,-32.093 h1.78
  text "6" at 336.182,-32.093 h1.78
M10 Fab Notes:
  drawing of 189 lines, arcs and shapes, not listed
  text "DESIGN INFORMATION" at 314.503,161.447 h1.52
  text "MIN. TRACK WIDTH:" at 298.131,158.091 h1.52
  text "8" at 325.976,158.091 h1.52
  text "MIL" at 329.907,158.091 h1.52
  text "MIN. CLEARANCE:" at 298.131,154.938 h1.52
  text "0.2" at 324.452,154.938 h1.52
  text "mm" at 329.907,154.938 h1.52
  text "MIN. VIA PAD SIZE:" at 298.131,151.785 h1.52
  text "24" at 325.214,151.785 h1.52
  text "MIL" at 329.907,151.785 h1.52
  text "0.05mm (2MIL)" at 315.784,148.486 h1.52
  text "MINIMUM ANNULAR RING" at 289.769,148.277 h1.52
  text "EXTERNAL" at 333.768,148.277 h1.52
  text "PER" at 294.849,145.48 h1.52
  text "IPC-D-275 CLASS 2 LEVEL C" at 300.437,145.48 h1.52
  text "MIL, HOLES" at 338.238,142.928 h1.52
  text "+/-" at 328.27,142.709 h1.52
  text "+/-" at 349.961,142.709 h1.52
  text "REGISTRATION TOLERANCES:" at 289.769,142.682 h1.52
  text "METAL" at 320.243,142.682 h1.52
  text "5" at 334.879,142.683 h1.52
  text "3" at 356.037,142.683 h1.52
  text "MIL" at 358.99,142.682 h1.52
  text "HOLE SIZE TOLERANCE (UNLESS OTHERWISE SPECIFIED):" at 289.769,140.185 h1.52
  text "+/-" at 349.961,140.112 h1.52
  text "3" at 356.037,140.085 h1.52
  text "MIL" at 358.99,140.085 h1.52
  text "MATERIAL:" at 287.87,136.589 h1.52
  text "FR-4 High Tg" at 312.926,133.324 h1.52
  text "X" at 309.257,133.122 h1.52
  text "FR-408" at 298.563,133.007 h1.52
  text "OTHER" at 336.358,133.007 h1.52
  text "62 MIL (1.6mm) +/-10%" at 306.694,129.374 h1.52
  text "X" at 303.643,129.312 h1.52
  text "THICKNESS:" at 289.769,129.165 h1.52
  text "OTHER" at 339.33,129.165 h1.52
  text "TOLERANCE:" at 289.769,125.652 h1.52
  text "X" at 311.314,125.652 h1.52
  text "ANSI IPC-6012 TYPE 3 CLASS 2" at 315.836,125.652 h1.52
  text "OTHER +/-" at 315.835,121.989 h1.52
  text "BOW & TWIST:" at 289.769,118.302 h1.52
  text "X" at 311.314,118.302 h1.52
  text "ANSI IPC-6012 TYPE 3 CLASS 2" at 315.836,118.302 h1.52
  text "OTHER +/-" at 315.835,114.576 h1.52
  text "DRILLING:" at 287.87,111.258 h1.52
  text "NC_DRILL FILES" at 332.599,108.586 h1.52
  text "REFERENCE:" at 289.769,108.486 h1.52
  text "X" at 306.463,108.484 h1.52
  text "AS SHOWN" at 310.984,108.486 h1.52
  text "X" at 329.348,108.486 h1.52
  text "OTHER" at 340.168,104.873 h1.52
  text "PTH COPPER THICKNESS:" at 289.761,104.783 h1.52
  text "X" at 318.697,104.783 h1.52
  text "20-30 um" at 321.948,104.783 h1.52
  text "BOARD FINISH:" at 287.87,101.034 h1.52
  text "SILKSCREEN:" at 291.812,98.237 h1.52
  text "X" at 316.14,98.237 h1.52
  text "TOP" at 319.112,98.237 h1.52
  text "X" at 329.094,98.237 h1.52
  text "BOTTOM" at 332.091,98.237 h1.52
  text "SILKSCREEN COLOR:" at 291.812,94.295 h1.52
  text "X" at 316.115,94.295 h1.52
  text "WHITE" at 319.112,94.295 h1.52
  text "OTHER" at 332.091,94.295 h1.52
  text "X" at 319.442,90.652 h1.52
  text "GREEN" at 322.439,90.652 h1.52
  text "OTHER" at 338.136,90.652 h1.52
  text "SOLDER RESIST COLOR:" at 291.812,90.477 h1.52
  text "X" at 319.442,86.734 h1.52
  text "MATTE" at 322.439,86.734 h1.52
  text "SEMI-GLOSS" at 338.125,86.717 h1.52
  text "IMMERSION GOLD (ENIG)" at 314.819,82.345 h1.52
  text "ENEPIG" at 348.793,82.162 h1.52
  text "SURFACE FINISH:" at 287.87,82.136 h1.52
  text "X" at 310.298,82.136 h1.52
  text "IMM. TIN/SILVER OR EQUIV" at 296.24,78.649 h1.52
  text "OTHER" at 332.599,78.549 h1.52
  text "ARRAY/PANEL:" at 287.87,74.602 h1.52
  text "CUT AND TRIM PER M1 BOARD OUTLINE" at 314.819,74.393 h1.52
  text "N.C. ROUTE" at 314.819,70.94 h1.52
  text "X" at 332.295,70.94 h1.52
  text "V. SCORE" at 336.816,70.94 h1.52
  text "CERTIFICATION:" at 287.87,67.66 h1.52
  text "MATERIALS AND WORKMANSHIP FOR ALL PCBS" at 306.285,67.66 h1.52
  text "TO MEET OR EXCEED THE REQUIREMENTS OF:" at 306.285,65.271 h1.52
  text "X" at 297.078,62.003 h1.52
  text "ANSI IPC-A-600F CLASS ->" at 300.329,62.003 h1.52
  text "X" at 342.188,62.003 h1.52
  text "2" at 344.982,62.003 h1.52
  text "1" at 336.981,61.965 h1.52
  text "3" at 353.973,61.965 h1.52
  text "X" at 317.702,58.252 h1.52
  text "RoHS" at 320.953,58.252 h1.52
  text "OTHER" at 337.321,58.252 h1.52
  text "PER ORDER" at 347.407,58.252 h1.52
  text "ALL BOARDS MUST MEET OR EXCEED UL94-V0 REQUIREMENTS." at 288.569,54.345 h1.52
  text "PCB MUST BEAR THE UL94V-0 UL REGISTERED MATERIAL ID NUMBER" at 288.569,51.397 h1.52
  text "ADDITIONAL REQUIREMENTS:" at 287.87,47.094 h1.52
  text "MICROSECTION:" at 289.769,44.373 h1.52
  text "YES" at 312.775,44.373 h1.52
  text "REQUIRED" at 334.657,40.707 h1.52
  text "BARE BOARD ELEC. TEST:" at 289.769,40.634 h1.52
  text "NONE" at 322.935,40.634 h1.52
  text "X" at 331.66,40.634 h1.52
  text "PER ORDER" at 349.693,40.634 h1.52
  text "XX MIL VIAS REQUIRE NON-CONDUCTIVE FILL AND PLANARIZE" at 294.04,35.428 h1.5
  text "XX MIL VIAS REQUIRE CONDUCTIVE FILL AND PLANARIZE" at 294.243,32.787 h1.52
  text "OUTER XX MIL TRACES REQUIRE 50 OHM SINGLE-ENDED IMPEDANCE" at 294.218,28.637 h1.47
  text "LAYER 2 & 3 (INNER LAYERS) XX MIL WIDE, XX MIL SPACE / TRACES REQUIRE 100 OHM DIFFERENTIAL IMPEDANCE" at 294.015,22.65 h1.52
  text ".Layer_Name" at 14.656,-21.806 h1.52
M11 Gerber Information:
  lines w0.254: -7.417,-23.626 160.223,-23.626 ; -7.417,-18.462 160.274,-18.462 ; -7.417,-13.297 -7.417,-28.791 94.31,-28.791 160.274,-28.791 160.274,-13.297 -7.404,-13.297 -7.404,-28.791 32.614,-28.791 ; 55.194,-28.791 55.194,-13.297 ; 87.376,-18.462 87.376,-13.297 ; 108.712,-18.462 108.712,-13.297 ; 124.511,-28.956 124.511,-23.804
  text "ALL ARTWORK VIEWED FROM TOP SIDE" at -5.804,-16.654 h1.52
  text "BOARD #:" at 57.099,-16.654 h1.52
  text ".PRJ_Number" at 70.955,-16.654 h1.52
  text "REV:" at 92.405,-16.654 h1.52
  text ".PCB_Rev" at 99.809,-16.654 h1.52
  text "SVN REV:" at 113.69,-16.654 h1.52
  text ".VersionControl_RevNumber" at 126.543,-16.654 h1.52
  text "LAYER NAME =" at -5.804,-21.806 h1.52
  text "TID #:" at 57.099,-21.819 h1.52
  text ".TID" at 70.955,-21.819 h1.52
  text "PLOT NAME =" at -5.804,-27.034 h1.52
  text ".plot_File_Name" at 14.656,-27.034 h1.52
  text "GENERATED    :" at 57.15,-27.034 h1.52
  text ".Print_Date" at 79.235,-27.034 h1.52
  text ".Print_Time" at 97.752,-27.034 h1.52
  text "TEXAS INSTRUMENTS" at 129.87,-27.034 h1.52
M12 Stackup:
  drawing of 295 lines, arcs and shapes, not listed
  text "Layer" at 249.469,186.879 h1.52
  text "Name" at 259.88,186.879 h1.52
  text "Material" at 283.496,186.879 h1.52
  text "Thickness" at 298.732,186.879 h1.52
  text "Constant" at 315.238,186.879 h1.52
  text "Board Layer Stack" at 329.712,186.879 h1.52
  text "Top Overlay" at 259.88,183.831 h1.52
  text "Top Solder" at 259.88,180.783 h1.52
  text "SM-001" at 283.496,180.783 h1.52
  text "1.00mil" at 298.732,180.783 h1.52
  text "4" at 315.238,180.783 h1.52
  text "1" at 249.469,177.735 h1.52
  text "Top Layer" at 259.88,177.735 h1.52
  text "CF-004" at 283.496,177.735 h1.52
  text "1.38mil" at 298.732,177.735 h1.52
  text "Dielectric 1" at 259.88,174.687 h1.52
  text "PP-022" at 283.496,174.687 h1.52
  text "8.20mil" at 298.732,174.687 h1.52
  text "4.5" at 315.238,174.687 h1.52
  text "2" at 249.469,171.639 h1.52
  text "Int1 (GND)" at 259.88,171.639 h1.52
  text "CF-004" at 283.496,171.639 h1.52
  text "1.38mil" at 298.732,171.639 h1.52
  text "Dielectric 3" at 259.88,168.591 h1.52
  text "Core-042" at 283.496,168.591 h1.52
  text "39.00mil" at 298.732,168.591 h1.52
  text "4.6" at 315.238,168.591 h1.52
  text "3" at 249.469,165.543 h1.52
  text "Int2 (PWR)" at 259.88,165.543 h1.52
  text "CF-004" at 283.496,165.543 h1.52
  text "1.38mil" at 298.732,165.543 h1.52
  text "Dielectric 5" at 259.88,162.495 h1.52
  text "PP-022" at 283.496,162.495 h1.52
  text "8.20mil" at 298.732,162.495 h1.52
  text "4.5" at 315.238,162.495 h1.52
  text "4" at 249.469,159.447 h1.52
  text "Bottom Layer" at 259.88,159.447 h1.52
  text "CF-004" at 283.496,159.447 h1.52
  text "1.38mil" at 298.732,159.447 h1.52
  text "Bottom Solder" at 259.88,156.399 h1.52
  text "SM-001" at 283.496,156.399 h1.52
  text "1.00mil" at 298.732,156.399 h1.52
  text "4" at 315.238,156.399 h1.52
  text "Bottom Overlay" at 259.88,153.351 h1.52
  text ".Layer_Name" at 14.656,-21.806 h1.52
M13 Component Bodies Top:
  text ".Layer_Name" at 14.656,-21.806 h1.52
M14 Component Bodies Bottom:
  text ".Layer_Name" at 14.656,-21.806 h1.52
M15 Courtyards Top:
  text ".Layer_Name" at 14.656,-21.806 h1.52
M16 Courtyards Bottom:
  text ".Layer_Name" at 14.656,-21.806 h1.52
Drill Drawing:
  lines w0.254: 135.534,76.938 135.534,77.289 135.884,77.639 135.534,77.989 135.534,78.339 135.884,78.339 136.234,77.989 136.584,78.339 136.934,78.339 136.934,77.989 136.584,77.639 136.934,77.289 136.934,76.938 136.584,76.938 136.234,77.289 135.884,76.938 135.534,76.938 ; 135.534,81.489 136.934,81.489 136.234,80.089 135.534,81.489 ; 135.534,83.239 136.234,83.589 136.934,83.239 136.584,83.939 136.934,84.639 136.234,84.289 135.534,84.639 135.884,83.939 135.534,83.239 ; 135.534,87.089 136.234,86.389 136.934,87.089 136.234,87.789 135.534,87.089
  lines w0.305: 134.264,75.993 216.225,75.993 ; 134.264,88.595 216.225,88.595 ; 142.833,72.843 142.833,91.745 ; 151.258,72.843 151.258,91.745 ; 167.409,72.843 167.409,91.745 ; 173.983,72.843 173.983,91.745 ; 183.501,72.843 183.501,91.745 ; 201.854,72.843 201.854,91.745 ; 134.264,72.843 216.225,72.843 216.225,91.745 134.264,91.745 134.264,72.843
  text "Symbol" at 136.155,89.54 h1.83
  text "Quantity" at 143.779,89.54 h1.83
  text "Finished Hole Size" at 152.204,89.54 h1.83
  text "Plated" at 168.354,89.54 h1.83
  text "Hole Type" at 174.928,89.54 h1.83
  text "Drill Layer Pair" at 184.446,89.54 h1.83
  text "Hole Tolerance" at 202.799,89.54 h1.83
  text "8" at 143.779,86.389 h1.52
  text "125.00mil (3.175mm)" at 152.204,86.389 h1.52
  text "NPTH" at 168.354,86.389 h1.52
  text "Round" at 174.928,86.389 h1.52
  text "Top Layer - Bottom Layer" at 184.446,86.389 h1.52
  text "38" at 143.779,83.239 h1.52
  text "10.00mil (0.254mm)" at 152.204,83.239 h1.52
  text "PTH" at 168.354,83.239 h1.52
  text "Round" at 174.928,83.239 h1.52
  text "Top Layer - Bottom Layer" at 184.446,83.239 h1.52
  text "40" at 143.779,80.089 h1.52
  text "40.16mil (1.020mm)" at 152.204,80.089 h1.52
  text "PTH" at 168.354,80.089 h1.52
  text "Round" at 174.928,80.089 h1.52
  text "Top Layer - Bottom Layer" at 184.446,80.089 h1.52
  text "5" at 143.779,76.938 h1.52
  text "63.00mil (1.600mm)" at 152.204,76.938 h1.52
  text "PTH" at 168.354,76.938 h1.52
  text "Round" at 174.928,76.938 h1.52
  text "Top Layer - Bottom Layer" at 184.446,76.938 h1.52
  text "91 Total" at 143.779,73.788 h1.52
  text ".Layer_Name" at 14.656,-21.806 h1.52
M17 Embedded Cavity:
  text ".Layer_Name" at 14.656,-21.806 h1.52
M18 Embedded Assembly:
  text ".Layer_Name" at 14.656,-21.806 h1.52
M19 Embedded Keepout:
  text ".Layer_Name" at 14.656,-21.806 h1.52

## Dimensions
0,-10.16 to 25.4,-10.16 on M2 Board Dimensions
0,0 to 115,120.25 on M2 Board Dimensions
0,0 to 10.147,-2.5 on M2 Board Dimensions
